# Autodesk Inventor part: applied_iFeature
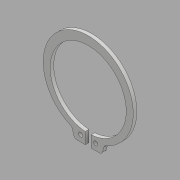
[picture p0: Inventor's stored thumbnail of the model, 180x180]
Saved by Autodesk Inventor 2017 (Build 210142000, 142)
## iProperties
Created: 2016-06
Part Number: applied_iFeature
Material: Generic
Document SubType Name: Modeling
Designer: CADCIM
Density: 1 g/cm^3
Appearance: Default
Author: CADCIM
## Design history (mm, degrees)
sketch "Sketch1"
  geometry: L1 (9.52, -25.305)-(8.665, -28.284); L2 (6.743, -29.733)-(1.75, -29.733); L3 (1.75, -29.733)-(1.75, -22.833); L4 (0, 0)-(0, -33.55); L5 (-6.743, -29.733)-(-1.75, -29.733); L6 (-1.75, -29.733)-(-1.75, -22.833); L7 (-9.52, -25.305)-(-8.665, -28.284); C1 r 1.25 at (4.55, -25.815); C2 r 1.25 at (-4.55, -25.815); A1 r 22.9 centre (0, 0) between (1.75, -22.833) and (-1.75, -22.833); A2 r 27.1 centre (0, 0.9) between (10.656, -24.017) and (-10.656, -24.017); A3 r 2 centre (-6.743, -27.733) between (-8.665, -28.284) and (-6.743, -29.733); A4 r 2 centre (-11.442, -25.856) between (-9.52, -25.305) and (-10.656, -24.017); A5 r 2 centre (11.442, -25.856) between (10.656, -24.017) and (9.52, -25.305); A6 r 2 centre (6.743, -27.733) between (6.743, -29.733) and (8.665, -28.284); 12 further points
  constraints: 18 point on circle, 14 end point, 8 centre point, 8 point on line, 8 tangent, 4 equal radius, 4 symmetric about line, 2 coincident, 2 midpoint, 1 horizontal, 1 horizontal alignment, 1 perpendicular, 1 vertical
  dimensions: "d0" = 45.8 diameter of A1; "d4" = 6.9 distance from line of L6.end L5; "d5" = 5.1 distance of point (0, 28) point (0, 22.9); "d6" = 2.5 diameter of C1; "d8" = 2 radius of A3 (derived); "d9" = 2.8 distance from line of C1.centre L3; "d10" = 3.5 distance of L5.end L2.end; "d11" = 27.1 radius of A2; "d14" = 6.5 distance of L5.end point (-8.25, -29.733); "d15" = 32 deg angle of L7 L1
extrude "Extrusion1" new body sketch "Sketch1" distance "d16" = 2.15; taper "d17" = 0 deg
body "Solid1"
